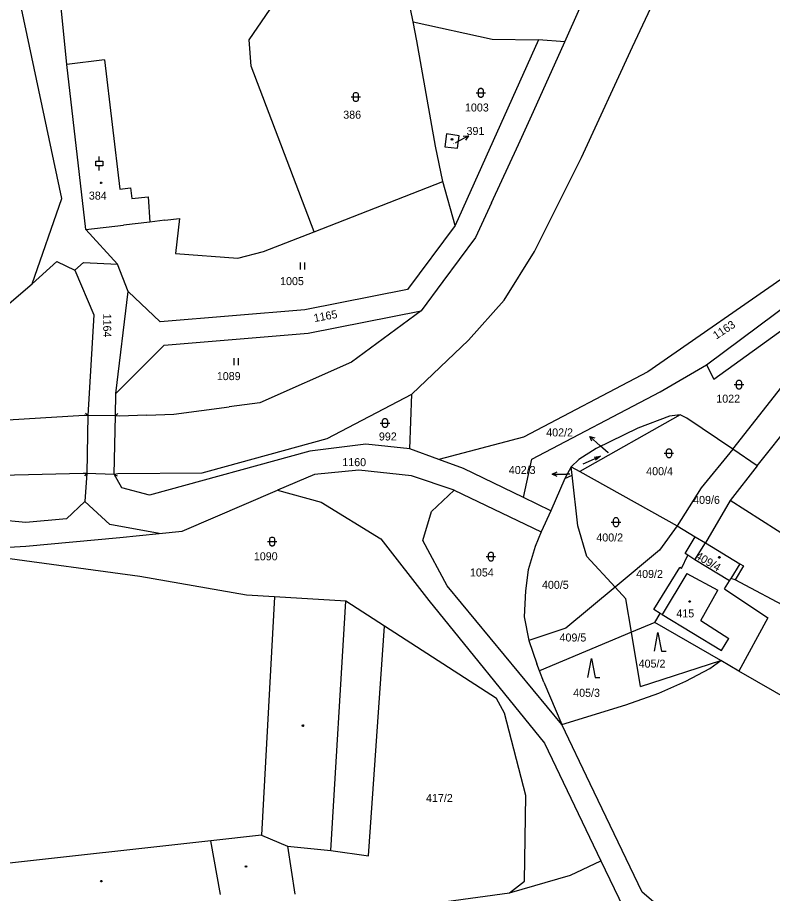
# Model space of a CAD drawing. Extents: x -812394 to -807601, y -1013097 to -1009266.
# Drawn here: x -810997.7 to -810837.2, y -1011724.6 to -1011538.5 of the extents above; entities that cross this region are included whole.
import ezdxf

# ---------------------------------------------------------------- set-up
doc = ezdxf.new("R2010")
doc.units = 0
for name, color, linetype in [('Default', 7, 'Continuous'), ('KN_HRANICE', 7, 'Continuous'), ('KN_KULTURY', 7, 'Continuous'), ('KN_PARCELY', 7, 'Continuous'), ('KN_SLUCKY', 7, 'Continuous')]:
    doc.layers.add(name, color=color, linetype=linetype)

# ---------------------------------------------------------------- blocks, each defined once
blk = doc.blocks.new('10292')
at = {"layer": 'Default'}
blk.add_line((0, 3), (0, 0), dxfattribs=at)
blk.add_lwpolyline([(-0.5, 2), (0, 3), (0.5, 2)], dxfattribs=at)
blk = doc.blocks.new('4201')
at = {"layer": 'Default'}
blk.add_line((0, 0), (-0.5, -0.5), dxfattribs=at)
blk = doc.blocks.new('306')
at = {"layer": 'Default'}
for p, q in [((-0.5, 1.5), (-0.5, 0)), ((0.5, 0), (0.5, 1.5))]:
    blk.add_line(p, q, dxfattribs=at)
blk = doc.blocks.new('308')
at = {"layer": 'Default'}
blk.add_lwpolyline([(-0.75, 0), (0, 4), (0.75, 0), (1.75, 0)], dxfattribs=at)
blk = doc.blocks.new('316')
at = {"layer": 'Default'}
for points in [[(-0.5, 1.5), (-0.4, 1.79), (-0.15, 1.97), (0.16, 1.97), (0.41, 1.79), (0.51, 1.5), (0.51, 0.5), (0.41, 0.21), (0.16, 0.03), (-0.15, 0.03), (-0.4, 0.21), (-0.5, 0.5), (-0.5, 1.5)], [(-1, 1), (0.27, 1), (1, 1)]]:
    blk.add_lwpolyline(points, dxfattribs=at)
blk = doc.blocks.new('802')
at = {"layer": 'Default'}
blk.add_line((-3, 0), (3, 0), dxfattribs=at)
blk.add_lwpolyline([(1, 0.5), (3, 0), (1, -0.5)], dxfattribs=at)
blk = doc.blocks.new('318')
at = {"layer": 'Default'}
blk.add_line((0, 2), (0, 3), dxfattribs=at)
blk.add_lwpolyline([(0, 0), (0, 1), (-0.75, 1), (-0.75, 2), (0, 2), (0.75, 2), (0.75, 1), (0, 1)], dxfattribs=at)
blk = doc.blocks.new('402')
at = {"layer": 'Default'}
blk.add_lwpolyline([(0.09, 0.15), (0.18, 0), (0.09, -0.15), (-0.09, -0.15), (-0.18, 0), (-0.09, 0.15), (0.09, 0.15)], dxfattribs=at)

msp = doc.modelspace()

# ---------------------------------------------------------------- linework, layer by layer
at = {"layer": 'KN_HRANICE'}
for p, q in [((-810988.29, -1011576.92), (-811004.66, -1011499.57)), ((-810913.6, -1011539.41), (-810916.42, -1011525.41)), ((-810987.2, -1011548.48), (-810988.82, -1011532.52)), ((-810948.4, -1011543.24), (-810941.47, -1011533.07)), ((-810881.34, -1011543.7), (-810878.11, -1011536.55)), ((-810913.6, -1011539.41), (-810896.75, -1011543.11)), ((-810912.78, -1011543.48), (-810913.6, -1011539.41)), ((-810948.04, -1011548.87), (-810948.4, -1011543.24)), ((-810908.81, -1011565.82), (-810912.78, -1011543.48)), ((-810886.95, -1011543.28), (-810904.65, -1011582.69)), ((-810896.75, -1011543.11), (-810886.95, -1011543.28)), ((-810888.01, -1011558.44), (-810881.34, -1011543.7)), ((-810881.34, -1011543.7), (-810886.95, -1011543.28)), ((-810983.14, -1011583.56), (-810987.2, -1011548.48)), ((-810934.61, -1011584.01), (-810948.04, -1011548.87)), ((-810907.28, -1011573.34), (-810908.81, -1011565.82)), ((-810934.61, -1011584.01), (-810907.28, -1011573.34)), ((-810904.65, -1011582.69), (-810907.28, -1011573.34)), ((-810994.59, -1011595.07), (-810988.29, -1011576.92)), ((-810896.93, -1011577.89), (-810900.33, -1011585.26)), ((-810966.35, -1011581.58), (-810969.54, -1011581.95)), ((-810966.35, -1011581.58), (-810963.27, -1011581.22)), ((-810963.27, -1011581.22), (-810964.13, -1011588.63)), ((-810983.14, -1011583.56), (-810975.16, -1011582.61)), ((-810976.41, -1011590.91), (-810983.14, -1011583.56)), ((-810969.54, -1011581.95), (-810975.16, -1011582.61)), ((-810904.65, -1011582.69), (-810914.75, -1011596.26)), ((-810945.41, -1011588.22), (-810934.61, -1011584.01)), ((-810900.33, -1011585.26), (-810907.25, -1011594.56)), ((-810964.13, -1011588.63), (-810950.86, -1011589.65)), ((-810950.86, -1011589.65), (-810945.41, -1011588.22)), ((-810994.59, -1011595.07), (-810989.3, -1011590.32)), ((-810989.3, -1011590.32), (-810985.49, -1011592.2)), ((-810985.49, -1011592.2), (-810983.65, -1011590.57)), ((-810983.65, -1011590.57), (-810976.41, -1011590.91)), ((-810974.14, -1011596.72), (-810976.41, -1011590.91)), ((-810985.49, -1011592.2), (-810981.49, -1011601.67)), ((-810831.4, -1011591.35), (-810863.67, -1011613.78)), ((-810907.25, -1011594.56), (-810911.89, -1011600.79)), ((-810851.23, -1011612.3), (-810827.53, -1011594.64)), ((-811020.14, -1011616.85), (-810994.59, -1011595.07)), ((-810976.79, -1011618.38), (-810974.14, -1011596.72)), ((-810967.38, -1011603.18), (-810974.14, -1011596.72)), ((-810914.75, -1011596.26), (-810936.59, -1011600.58)), ((-810849.63, -1011615.36), (-810824.29, -1011596.97)), ((-810981.49, -1011601.67), (-810982.75, -1011623.07)), ((-810936.59, -1011600.58), (-810967.38, -1011603.18)), ((-810935.89, -1011605.54), (-810911.89, -1011600.79)), ((-810966.54, -1011608.13), (-810935.89, -1011605.54)), ((-810976.79, -1011618.38), (-810966.54, -1011608.13)), ((-810861.07, -1011618.06), (-810851.23, -1011612.3)), ((-810851.23, -1011612.3), (-810849.63, -1011615.36)), ((-810863.67, -1011613.78), (-810890.13, -1011627.65)), ((-810840.43, -1011633.72), (-810825.11, -1011614.6)), ((-810976.85, -1011623.16), (-810976.79, -1011618.38)), ((-810914.28, -1011630.13), (-810913.82, -1011618.49)), ((-810888.31, -1011632.34), (-810861.07, -1011618.06)), ((-810976.85, -1011623.16), (-810982.75, -1011623.07)), ((-810856.83, -1011622.91), (-810878.14, -1011634.96)), ((-810859.07, -1011623.17), (-810865.83, -1011625.76)), ((-810856.83, -1011622.91), (-810859.07, -1011623.17)), ((-810855.38, -1011623.6), (-810856.83, -1011622.91)), ((-810845.57, -1011630.24), (-810855.38, -1011623.6)), ((-810865.83, -1011625.76), (-810874.64, -1011630.05)), ((-810890.13, -1011627.65), (-810908.12, -1011632.39)), ((-810923.64, -1011629.14), (-810935.55, -1011630.66)), ((-810914.28, -1011630.13), (-810923.64, -1011629.14)), ((-810908.12, -1011632.39), (-810914.28, -1011630.13)), ((-810874.64, -1011630.05), (-810878.34, -1011632.37)), ((-810845.57, -1011630.24), (-810852.3, -1011638.43)), ((-810840.43, -1011633.72), (-810845.57, -1011630.24)), ((-810935.55, -1011630.66), (-810969.6, -1011639.97)), ((-810902.89, -1011634.32), (-810908.12, -1011632.39)), ((-810890.13, -1011640.47), (-810888.31, -1011632.34)), ((-810879.94, -1011633.96), (-810881.3, -1011636.47)), ((-810878.34, -1011632.37), (-810879.94, -1011633.96)), ((-810879.75, -1011635.73), (-810879.94, -1011633.96)), ((-810879.94, -1011633.96), (-810878.14, -1011634.96)), ((-810840.43, -1011633.72), (-810846.16, -1011641.14)), ((-810982.94, -1011635.34), (-810983.35, -1011641.36)), ((-810982.94, -1011635.34), (-810977.14, -1011635.5)), ((-810975.48, -1011638.44), (-810977.14, -1011635.5)), ((-810934.57, -1011635.58), (-810942.44, -1011638.95)), ((-810925.1, -1011634.66), (-810934.57, -1011635.58)), ((-810913.89, -1011635.85), (-810925.1, -1011634.66)), ((-810904.85, -1011638.92), (-810913.89, -1011635.85)), ((-810890.13, -1011640.47), (-810902.89, -1011634.32)), ((-810881.3, -1011636.47), (-810879.75, -1011635.73)), ((-810878.58, -1011646.5), (-810879.75, -1011635.73)), ((-810878.14, -1011634.96), (-810857.44, -1011646.51)), ((-810881.3, -1011636.47), (-810884.27, -1011643.3)), ((-810969.6, -1011639.97), (-810975.48, -1011638.44)), ((-810962.69, -1011647.62), (-810942.44, -1011638.95)), ((-810942.44, -1011638.95), (-810933.12, -1011641.48)), ((-810909.69, -1011643.43), (-810904.85, -1011638.92)), ((-810904.85, -1011638.92), (-810886.34, -1011647.79)), ((-810852.3, -1011638.43), (-810857.44, -1011646.51)), ((-810983.35, -1011641.36), (-810987.28, -1011645)), ((-810978.06, -1011646.24), (-810983.35, -1011641.36)), ((-810884.27, -1011643.3), (-810890.13, -1011640.47)), ((-810846.16, -1011641.14), (-810851.41, -1011650.14)), ((-810825.68, -1011654.24), (-810846.16, -1011641.14)), ((-810933.12, -1011641.48), (-810920.45, -1011649.26)), ((-810884.27, -1011643.3), (-810886.34, -1011647.79)), ((-810995.89, -1011645.77), (-811016.44, -1011643.9)), ((-810987.28, -1011645), (-810995.89, -1011645.77)), ((-810911.51, -1011649.61), (-810909.69, -1011643.43)), ((-810967.59, -1011648.15), (-810978.06, -1011646.24)), ((-810876.64, -1011652.99), (-810878.58, -1011646.5)), ((-810857.44, -1011646.51), (-810861.19, -1011651.67)), ((-810857.44, -1011646.51), (-810853.61, -1011648.83)), ((-810975.92, -1011649.01), (-810967.59, -1011648.15)), ((-810967.59, -1011648.15), (-810962.69, -1011647.62)), ((-810886.34, -1011647.79), (-810887.64, -1011650.91)), ((-810855.74, -1011652.37), (-810853.61, -1011648.83)), ((-810853.61, -1011648.83), (-810851.41, -1011650.14)), ((-810995.89, -1011650.79), (-810975.92, -1011649.01)), ((-810920.45, -1011649.26), (-810910.24, -1011662.33)), ((-810906.32, -1011659.22), (-810911.51, -1011649.61)), ((-810851.41, -1011650.14), (-810844.12, -1011654.56)), ((-811011.38, -1011651.85), (-810995.89, -1011650.79)), ((-810971.7, -1011657.24), (-811011.38, -1011651.85)), ((-810887.64, -1011650.91), (-810889.14, -1011655.88)), ((-810861.19, -1011651.67), (-810870.64, -1011659.53)), ((-810855.16, -1011652.74), (-810855.74, -1011652.37)), ((-810870.64, -1011659.53), (-810876.64, -1011652.99)), ((-810856.54, -1011655.55), (-810855.16, -1011652.74)), ((-810853.65, -1011653.71), (-810855.16, -1011652.74)), ((-810846.33, -1011658.17), (-810853.65, -1011653.71)), ((-810889.14, -1011655.88), (-810889.71, -1011660.31)), ((-810862.38, -1011664.26), (-810856.89, -1011655.34)), ((-810856.54, -1011655.55), (-810856.89, -1011655.34)), ((-810843.35, -1011655.03), (-810845.13, -1011657.96)), ((-810844.12, -1011654.56), (-810843.35, -1011655.03)), ((-810948.98, -1011661.21), (-810971.7, -1011657.24)), ((-810847.39, -1011659.86), (-810846.33, -1011658.17)), ((-810846.33, -1011658.17), (-810846.01, -1011657.66)), ((-810845.13, -1011657.96), (-810846.01, -1011657.66)), ((-810820.6, -1011671.03), (-810845.13, -1011657.96)), ((-810881.94, -1011688.74), (-810906.32, -1011659.22)), ((-810870.64, -1011659.53), (-810881.07, -1011668.21)), ((-810868.35, -1011662.02), (-810870.64, -1011659.53)), ((-810847.39, -1011659.86), (-810838.13, -1011666.01)), ((-810943.04, -1011661.57), (-810948.98, -1011661.21)), ((-810927.88, -1011662.52), (-810943.04, -1011661.57)), ((-810889.71, -1011660.31), (-810889.93, -1011665.8)), ((-810919.67, -1011667.84), (-810927.88, -1011662.52)), ((-810910.24, -1011662.33), (-810885.61, -1011692.65)), ((-810867.17, -1011669.11), (-810868.35, -1011662.02)), ((-810861.06, -1011665.11), (-810862.38, -1011664.26)), ((-810862.16, -1011667.01), (-810861.06, -1011665.11)), ((-810889.93, -1011665.8), (-810888.97, -1011670.87)), ((-810862.16, -1011667.01), (-810867.17, -1011669.11)), ((-810848.18, -1011675.13), (-810862.16, -1011667.01)), ((-810838.13, -1011666.01), (-810844.35, -1011677.34)), ((-810923.04, -1011716.62), (-810919.67, -1011667.84)), ((-810895.87, -1011683.21), (-810919.67, -1011667.84)), ((-810881.07, -1011668.21), (-810888.97, -1011670.87)), ((-810867.17, -1011669.11), (-810886.7, -1011677.32)), ((-810865.26, -1011680.6), (-810867.17, -1011669.11)), ((-810888.97, -1011670.87), (-810887.26, -1011675.84)), ((-810886.7, -1011677.32), (-810887.26, -1011675.84)), ((-810865.26, -1011680.6), (-810848.18, -1011675.13)), ((-810850.5, -1011676.82), (-810848.18, -1011675.13)), ((-810844.35, -1011677.34), (-810848.18, -1011675.13)), ((-810885.79, -1011679.69), (-810886.7, -1011677.32)), ((-810855.6, -1011679.52), (-810850.5, -1011676.82)), ((-810828.27, -1011686.59), (-810844.35, -1011677.34)), ((-810885.79, -1011679.69), (-810881.94, -1011688.74)), ((-810861.34, -1011682.08), (-810855.6, -1011679.52)), ((-810868.35, -1011684.5), (-810861.34, -1011682.08)), ((-810894.15, -1011686.31), (-810895.87, -1011683.21)), ((-810881.94, -1011688.74), (-810868.35, -1011684.5)), ((-810889.63, -1011703.76), (-810894.15, -1011686.31)), ((-810875.9, -1011701.34), (-810881.94, -1011688.74)), ((-810885.61, -1011692.65), (-810873.63, -1011717.68)), ((-810864.89, -1011724.35), (-810875.9, -1011701.34)), ((-810889.92, -1011721.98), (-810889.63, -1011703.76)), ((-810940.3, -1011714.57), (-810931.06, -1011715.46)), ((-810940.3, -1011714.57), (-810938.7, -1011724.76)), ((-810931.06, -1011715.46), (-810923.04, -1011716.62)), ((-810880.1, -1011720.69), (-810873.63, -1011717.68)), ((-810873.63, -1011717.68), (-810868.94, -1011727.48)), ((-810893.06, -1011724.45), (-810880.1, -1011720.69)), ((-810893.06, -1011724.45), (-810889.92, -1011721.98)), ((-810920.02, -1011728.18), (-810893.06, -1011724.45)), ((-810846.21, -1011740.05), (-810864.89, -1011724.35))]:
    msp.add_line(p, q, dxfattribs=at)
for points in [[(-810887.79, -1011588.2), (-810877.76, -1011568.21), (-810866.95, -1011544.7), (-810857.48, -1011524.61), (-810845.94, -1011498.21), (-810817.11, -1011436.78)], [(-810896.93, -1011577.89), (-810891.18, -1011565.46), (-810888.01, -1011558.44)], [(-810913.82, -1011618.49), (-810901.8, -1011607.05), (-810894.25, -1011598.54), (-810887.79, -1011588.2)], [(-810845.57, -1011630.24), (-810834.41, -1011616.01), (-810814.84, -1011590.15)], [(-810911.89, -1011600.79), (-810926.65, -1011611.75), (-810946.18, -1011620.4), (-810952.71, -1011621.24)], [(-810956.88, -1011634.82), (-810931.83, -1011627.95), (-810913.82, -1011618.49)], [(-810970.17, -1011622.97), (-810964.43, -1011622.75), (-810952.71, -1011621.24)], [(-810982.75, -1011623.07), (-810983.49, -1011623.04), (-811005.6, -1011624.4)], [(-810970.17, -1011622.97), (-810976.1, -1011623.19), (-810976.85, -1011623.16)], [(-811029.29, -1011645.78), (-811020.71, -1011639.62), (-811010, -1011635.94), (-810983.72, -1011635.29), (-810982.94, -1011635.34)], [(-810977.14, -1011635.5), (-810976.39, -1011635.39), (-810958.42, -1011635.24), (-810956.88, -1011634.82)]]:
    msp.add_lwpolyline(points, dxfattribs=at)
msp.add_lwpolyline([(-810906.8, -1011565.95), (-810904.15, -1011566.29), (-810903.81, -1011563.64), (-810906.45, -1011563.25)], close=True, dxfattribs=at)
at = {"layer": 'KN_PARCELY'}
for p, q in [((-810904.55, -1011565.14), (-810904.44, -1011565.08)), ((-810872.12, -1011630.99), (-810873.78, -1011629.5)), ((-810880.24, -1011635.49), (-810880.98, -1011635.49))]:
    msp.add_line(p, q, dxfattribs=at)
at = {"layer": 'KN_SLUCKY'}
for p, q in [((-810979.2, -1011547.53), (-810987.2, -1011548.48)), ((-810979.2, -1011547.53), (-810975.94, -1011574.98)), ((-810975.94, -1011574.98), (-810973.66, -1011574.71)), ((-810973.66, -1011574.71), (-810973.39, -1011576.98)), ((-810973.39, -1011576.98), (-810969.94, -1011576.57)), ((-810969.94, -1011576.57), (-810969.54, -1011581.95)), ((-810982.75, -1011623.07), (-810982.94, -1011635.34)), ((-810977.14, -1011635.5), (-810976.85, -1011623.16)), ((-810853.65, -1011653.71), (-810851.41, -1011650.14)), ((-810844.12, -1011654.56), (-810846.01, -1011657.66)), ((-810855.41, -1011656.64), (-810860.65, -1011665.37)), ((-810855.41, -1011656.64), (-810848.77, -1011660.2)), ((-810943.04, -1011661.57), (-810945.82, -1011712.25)), ((-810852.43, -1011666.59), (-810848.77, -1011660.2)), ((-810931.06, -1011715.46), (-810927.88, -1011662.52)), ((-810860.65, -1011665.37), (-810861.06, -1011665.11)), ((-810860.65, -1011665.37), (-810848.03, -1011672.95)), ((-810852.43, -1011666.59), (-810846.42, -1011670.43)), ((-810848.03, -1011672.95), (-810846.42, -1011670.43)), ((-810956.56, -1011713.43), (-811006.65, -1011718.94)), ((-810945.82, -1011712.25), (-810956.56, -1011713.43)), ((-810954.56, -1011724.79), (-810956.56, -1011713.43)), ((-810945.82, -1011712.25), (-810940.3, -1011714.57))]:
    msp.add_line(p, q, dxfattribs=at)

# ---------------------------------------------------------------- block references
at = {"layer": 'KN_KULTURY'}
for name, p in [('316', (-810899.19, -1011555.5)), ('316', (-810925.75, -1011556.38)), ('402', (-810905.32, -1011564.38)), ('318', (-810980.31, -1011571.03)), ('402', (-810979.91, -1011573.6)), ('306', (-810937.11, -1011592.02)), ('306', (-810951.22, -1011612.37)), ('316', (-810844.29, -1011617.5)), ('316', (-810919.55, -1011625.66)), ('316', (-810859.18, -1011632.08)), ('316', (-810870.44, -1011646.72)), ('316', (-810943.55, -1011650.85)), ('316', (-810897.03, -1011654.03)), ('402', (-810848.46, -1011653.19)), ('402', (-810854.78, -1011662.56)), ('308', (-810861.51, -1011673.14)), ('308', (-810875.65, -1011678.71)), ('402', (-810937.02, -1011688.96)), ('402', (-810949.11, -1011718.86)), ('402', (-810979.87, -1011721.99))]:
    msp.add_blockref(name, p, dxfattribs=at)
at = {"layer": 'KN_KULTURY', "xscale": 0.67, "yscale": 0.67, "rotation": 24.637185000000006}
msp.add_blockref('802', (-810875.56, -1011632.52), dxfattribs=at)
at = {"layer": 'KN_PARCELY'}
for p, rotation in [((-810904.44, -1011565.08), -61.71817200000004), ((-810873.78, -1011629.5), 48.185750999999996), ((-810880.98, -1011635.49), 90.01166999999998)]:
    msp.add_blockref('10292', p, dxfattribs=dict(at, rotation=rotation))
at = {"layer": 'KN_SLUCKY'}
for p, rotation in [((-810982.75, -1011623.07), -90.07958300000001), ((-810976.85, -1011623.16), -178.02860400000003), ((-810977.14, -1011635.5), 105.53882599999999)]:
    msp.add_blockref('4201', p, dxfattribs=dict(at, rotation=rotation))
msp.add_blockref('4201', (-810982.94, -1011635.34), dxfattribs=at)

# ---------------------------------------------------------------- texts
at = {"layer": 'KN_PARCELY'}
for s, height, p in [('1003', 1.7, (-810902.55, -1011558.47)), ('386', 1.7, (-810928.43, -1011560)), ('391', 1.7, (-810902.22, -1011563.46)), ('391', 0.1, (-810905.12, -1011565.29)), ('384', 1.7, (-810982.51, -1011577.19)), ('1005', 1.7, (-810941.86, -1011595.36)), ('1089', 1.7, (-810955.31, -1011615.54)), ('1022', 1.7, (-810849.11, -1011620.33)), ('402/2', 1.7, (-810885.27, -1011627.5)), ('992', 1.7, (-810920.85, -1011628.36)), ('1160', 1.7, (-810928.63, -1011633.82)), ('402/2', 0.1, (-810872.36, -1011630.99)), ('402/3', 1.7, (-810893.23, -1011635.49)), ('400/4', 1.7, (-810864.02, -1011635.74)), ('402/3', 0.1, (-810880.48, -1011635.49)), ('409/6', 1.7, (-810854.04, -1011641.84)), ('400/2', 1.7, (-810874.62, -1011649.82)), ('1090', 1.7, (-810947.44, -1011653.82)), ('1054', 1.7, (-810901.49, -1011657.26)), ('409/2', 1.7, (-810866.15, -1011657.57)), ('400/5', 1.7, (-810886.18, -1011659.88)), ('415', 1.7, (-810857.61, -1011665.95)), ('409/5', 1.7, (-810882.44, -1011671.07)), ('405/2', 1.7, (-810865.62, -1011676.62)), ('405/3', 1.7, (-810879.54, -1011682.82)), ('417/2', 1.7, (-810910.83, -1011705.17))]:
    msp.add_text(s, height=height, dxfattribs=at).set_placement(p)
for s, rotation, p in [('1164', 269.978, (-810979.46, -1011601.41)), ('1165', 10.313, (-810934.54, -1011603.21)), ('1163', 33.403, (-810849.12, -1011606.95)), ('409/4', 329.279, (-810853.7, -1011653.35))]:
    msp.add_text(s, height=1.7, rotation=rotation, dxfattribs=at).set_placement(p)

doc.saveas('drawing.dxf')
